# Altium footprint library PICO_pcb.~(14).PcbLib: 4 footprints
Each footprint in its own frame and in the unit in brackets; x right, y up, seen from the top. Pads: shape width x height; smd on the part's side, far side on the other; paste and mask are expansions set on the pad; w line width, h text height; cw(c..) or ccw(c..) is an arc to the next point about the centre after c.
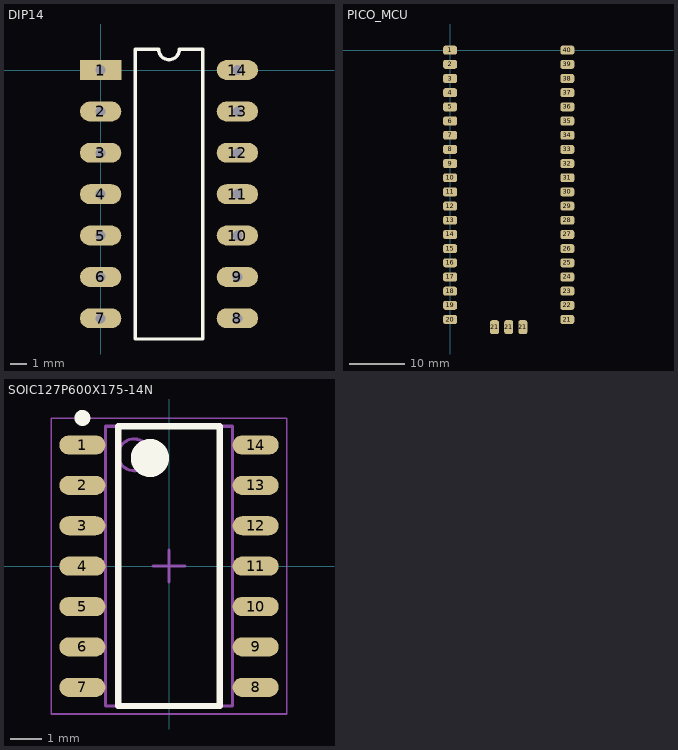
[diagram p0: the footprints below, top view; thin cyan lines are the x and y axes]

## DIP14 [mm]
pads (14):
  rect 2.5x1.2 hole 0.6: 1(0,0)
  oval 2.5x1.2 hole 0.6: 2(0,-2.5) 3(0,-5) 4(0,-7.5) 5(0,-10) 6(0,-12.5) 7(0,-15) 8(8.26,-15) 9(8.26,-12.5) 10(8.26,-10) 11(8.26,-7.5) 12(8.26,-5) 13(8.26,-2.5) 14(8.26,0)
Top Overlay:
  lines w0.2: 2.085,-16.25 2.085,1.25 3.505,1.25 ccw(c4.13,1.25) 4.755,1.25 6.175,1.25 6.175,-16.25 2.085,-16.25

## PCBComponent_1 - duplicate [mm]

## PICO_MCU [mm]
pads (43):
  rrect50% 2.5x1.6 smd: 1(0,0) 2(0,-2.54) 3(0,-5.08) 4(0,-7.62) 5(0,-10.16) 6(0,-12.7) 7(0,-15.24) 8(0,-17.78) 9(0,-20.32) 10(0,-22.86) 11(0,-25.4) 12(0,-27.94) 13(0,-30.48) 14(0,-33.02) 15(0,-35.56) 16(0,-38.1) 17(0,-40.64) 18(0,-43.18) 19(0,-45.72) 20(0,-48.26) 21(21,-48.26) 22(21,-45.72) 23(21,-43.18) 24(21,-40.64) 25(21,-38.1) 26(21,-35.56) 27(21,-33.02) 28(21,-30.48) 29(21,-27.94) 30(21,-25.4) 31(21,-22.86) 32(21,-20.32) 33(21,-17.78) 34(21,-15.24) 35(21,-12.7) 36(21,-10.16) 37(21,-7.62) 38(21,-5.08) 39(21,-2.54) 40(21,0)
  rrect50% 1.6x2.5 smd: 21(7.96,-49.63) 21(10.5,-49.63) 21(13.04,-49.63)
Bottom Overlay:
  lines w0.254: -3,-51.75 23.75,-51.75 ; -3,-51.75 -3,-51.75 ; -3,-51.75 -3,1.5 -2.5,2 23.75,2 23.75,-51.75 ; 23.75,-51.75 23.75,-51.75
3D body "Pico-R3.step": height 3.23, standoff -0.5, extent 0,-49.65 21,2.65

## SOIC127P600X175-14N [mm] "SOIC, 14-Leads, Body 8.65x3.90mm, Pitch 1.27mm, IPC Medium Density"
height 1.75
pads (14):
  oval 1.45x0.6 smd: 1(-2.725,3.81) 2(-2.725,2.54) 3(-2.725,1.27) 4(-2.725,0) 5(-2.725,-1.27) 6(-2.725,-2.54) 7(-2.725,-3.81) 8(2.725,-3.81) 9(2.725,-2.54) 10(2.725,-1.27) 11(2.725,0) 12(2.725,1.27) 13(2.725,2.54) 14(2.725,3.81)
Top Overlay:
  circle w0.6: c-0.6,3.4 r0.3
  circle w0.25: c-2.725,4.66 r0.125
  lines w0.2: -1.6,-4.4 1.6,-4.4 1.6,4.4 -1.6,4.4 -1.6,-4.4
Mechanical 13:
  circle w0.1: c-1.1,3.5 r0.5
  lines w0.1: -2,-4.4 2,-4.4 2,4.4 -2,4.4 -2,-4.4
Mechanical 15:
  lines w0.05: -3.7,-4.65 3.7,-4.65 3.7,4.65 -3.7,4.65 -3.7,-4.65
  lines w0.1: -0.5,0 0.5,0 ; 0,-0.5 0,0.5
3D body: height 1.75, standoff 0.25, extent -2,-4.4 2,4.4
